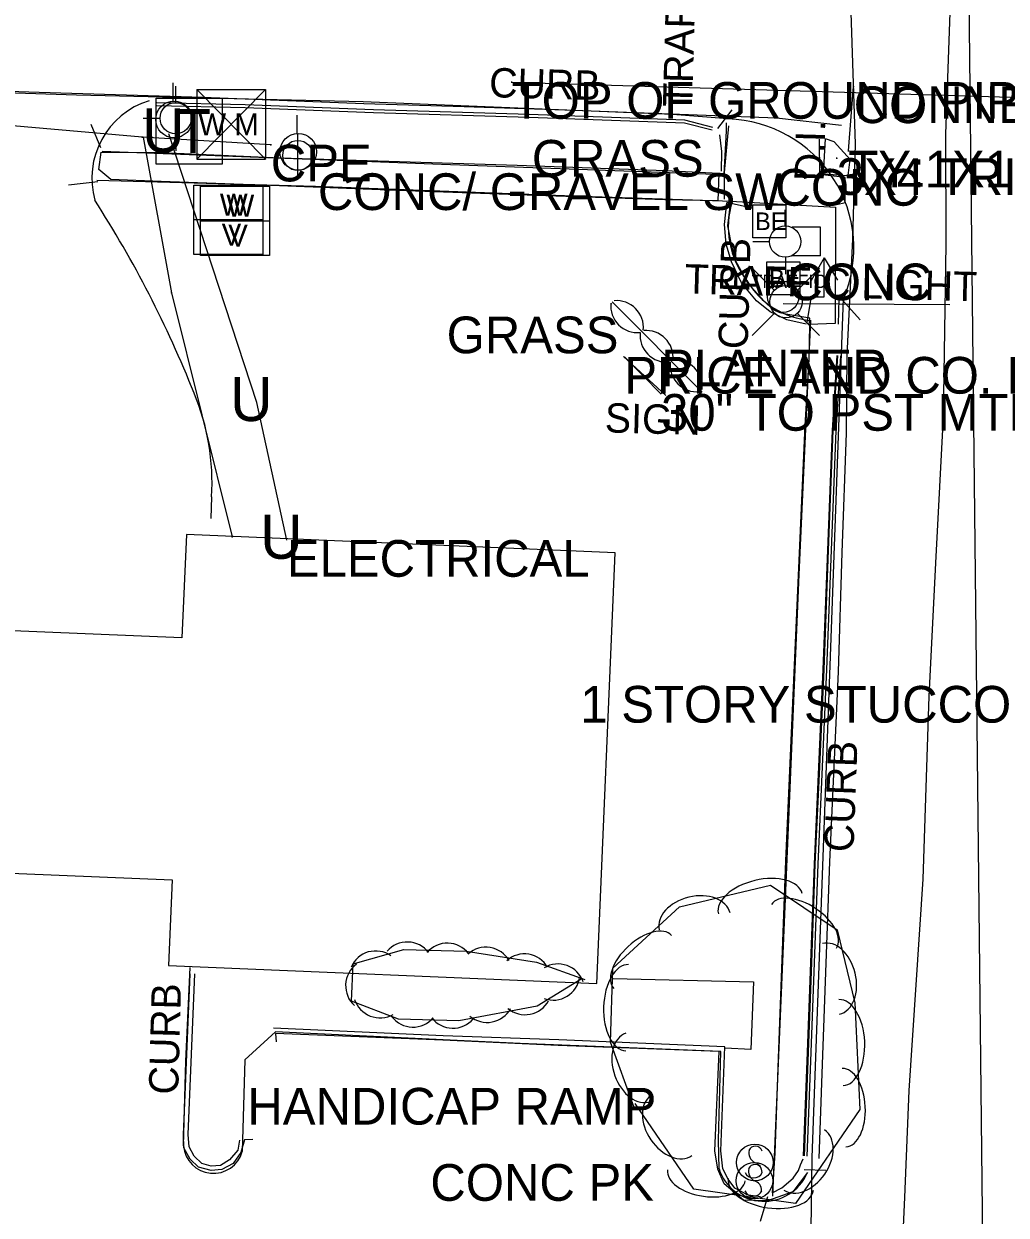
# Model space of a CAD drawing. Extents: x 978516 to 993312, y 1836504 to 1846212.
# Drawn here: x 992368 to 992501.8, y 1843226.3 to 1843388.6 of the extents above; entities that cross this region are included whole.
import ezdxf

# ---------------------------------------------------------------- set-up
doc = ezdxf.new("R2010")
doc.units = 0
for name, color, linetype in [('Default', 7, 'Continuous'), ('S_BASELINE', 7, 'Continuous'), ('S_BUILDING', 7, 'Continuous'), ('S_CURB', 7, 'Continuous'), ('S_CURB_ANNOT', 7, 'Continuous'), ('S_DRG_PT_SYM', 7, 'Continuous'), ('S_DRIVEWAY', 7, 'Continuous'), ('S_DROP_INLET', 7, 'Continuous'), ('S_DROP_INLET_ANNOT', 7, 'Continuous'), ('S_EDGE_CONCRETE', 7, 'Continuous'), ('S_EDGE_PAVEMENT', 7, 'Continuous'), ('S_ELECTRIC_UTILITIES', 7, 'Continuous'), ('S_GAS_UTILITIES', 7, 'Continuous'), ('S_GAS_UTILITIES_ANNOT', 7, 'Continuous'), ('S_PARKING', 7, 'Continuous'), ('S_PAVEMENT_CROWN', 7, 'Continuous'), ('S_SIDEWALK', 7, 'Continuous'), ('S_SIGN', 7, 'Continuous'), ('S_SIGN_ANNOT', 7, 'Continuous'), ('S_STORM_SEWER', 7, 'Continuous'), ('S_STORM_SEWER_ANNOT', 7, 'Continuous'), ('S_SURVEY_TEXT_ANNOT', 7, 'Continuous'), ('S_TELEPHONE_UTILITIES', 7, 'Continuous'), ('S_TRAFFIC_SIGNAL_ANNOT', 7, 'Continuous'), ('S_TREE', 7, 'Continuous'), ('S_UNDERGROUND_CABLE', 7, 'Continuous'), ('S_UNDERGROUND_CABLE_ANNOT', 7, 'Continuous'), ('S_UTILITY_POLE', 7, 'Continuous'), ('S_UTL_PT_SYM', 7, 'Continuous'), ('S_WATER_UTILITIES', 7, 'Continuous')]:
    doc.layers.add(name, color=color, linetype=linetype)

msp = doc.modelspace()

# ---------------------------------------------------------------- linework, layer by layer
at = {"layer": 'S_BASELINE'}
msp.add_line((992491.43, 1843870.1), (992499.58, 1843129.46), dxfattribs=at)
at = {"layer": 'S_BUILDING'}
msp.add_lwpolyline([(992387.68, 1843260.35), (992446.05, 1843257.87), (992448.54, 1843316.56), (992390.13, 1843319.04), (992389.53, 1843304.94), (992364.24, 1843306.02), (992362.84, 1843273.06), (992388.18, 1843271.98)], close=True, dxfattribs=at)
at = {"layer": 'S_CURB'}
for points in [[(992461.76, 1843374.1), (992457.97, 1843375.05), (992436.8, 1843375.84), (992415.61, 1843376.49), (992398.14, 1843377.15), (992386.1, 1843377.44)], [(992461.86, 1843374.49), (992458.03, 1843375.45), (992436.82, 1843376.24), (992415.62, 1843376.89), (992398.15, 1843377.55), (992386.11, 1843377.84)], [(992462.51, 1843374.34), (992464.47, 1843376.9)], [(992378.49, 1843371.69), (992377.17, 1843374.88)], [(992463.04, 1843368.53), (992463.07, 1843371.22), (992462.79, 1843373.49)], [(992378.08, 1843367.07), (992374.08, 1843366.61)], [(992474.55, 1843347.7), (992471.91, 1843348.28), (992469.67, 1843349.36), (992467.81, 1843350.86), (992465.73, 1843353.32), (992464.39, 1843356.17), (992463.65, 1843358.57), (992463.42, 1843361.25), (992463.73, 1843364.21)], [(992463.75, 1843364.29), (992467.14, 1843363.55)], [(992474.68, 1843347.91), (992475.28, 1843351.52)], [(992479.11, 1843351.41), (992481.89, 1843348.27)], [(992479.01, 1843351.15), (992478.93, 1843347.68)], [(992478.84, 1843343.41), (992478.19, 1843333.19), (992477.57, 1843316.92), (992476.94, 1843300.64), (992476.35, 1843287.39), (992475.75, 1843274.14), (992475.26, 1843260.72), (992474.76, 1843247.3), (992474.26, 1843234.39)], [(992479.24, 1843343.39), (992478.59, 1843333.17), (992477.97, 1843316.9), (992477.34, 1843300.63), (992476.75, 1843287.38), (992476.15, 1843274.13), (992475.66, 1843260.7), (992475.16, 1843247.28), (992474.66, 1843234.38)], [(992397.36, 1843236.54), (992397.14, 1843235.17), (992396.02, 1843233.84), (992394.76, 1843233.1), (992393.49, 1843233.01), (992392.23, 1843233.36), (992391.19, 1843234.34), (992390.49, 1843235.62), (992390.36, 1843237.3), (992391.29, 1843259.21)], [(992468.33, 1843228.81), (992466.38, 1843229.09), (992466.47, 1843229.16), (992464.85, 1843230.02), (992463.93, 1843231.23), (992463.21, 1843232.65), (992462.94, 1843235.09), (992463.48, 1843249.24), (992440.87, 1843250.2), (992425.09, 1843250.74), (992402.01, 1843251.81)], [(992474.27, 1843232.53), (992477.22, 1843232.45)], [(992469.29, 1843228.81), (992468.29, 1843225.47)]]:
    msp.add_lwpolyline(points, dxfattribs=at)
at = {"layer": 'S_DRG_PT_SYM'}
msp.add_lwpolyline([(992478.71, 1843370.29), (992478.71, 1843370.33), (992478.71, 1843370.29), (992478.66, 1843370.29), (992478.71, 1843370.29), (992478.71, 1843370.23), (992478.71, 1843370.29), (992478.76, 1843370.29)], dxfattribs=at)
at = {"layer": 'S_DRIVEWAY'}
msp.add_lwpolyline([(992474.73, 1843232.14), (992472.74, 1843229.52), (992469.28, 1843228.26), (992466.01, 1843228.38), (992463.37, 1843230.6)], dxfattribs=at)
at = {"layer": 'S_DROP_INLET'}
msp.add_lwpolyline([(992477.14, 1843372.93), (992476.88, 1843368.15), (992480.29, 1843367.93), (992480.56, 1843370.12), (992478.38, 1843372.54), (992477.2, 1843372.92)], dxfattribs=at)
at = {"layer": 'S_EDGE_CONCRETE'}
for points in [[(992463.43, 1843364.73), (992463.45, 1843368.36), (992464, 1843374.72)], [(992478.75, 1843363.98), (992479.87, 1843364.26), (992479.88, 1843367.67), (992476.4, 1843368.06), (992476.37, 1843372.9)]]:
    msp.add_lwpolyline(points, dxfattribs=at)
msp.add_lwpolyline([(992478.5, 1843347.79), (992474.96, 1843347.65), (992475.06, 1843348.51), (992471.79, 1843349.05), (992471.02, 1843349.25), (992470.06, 1843349.64), (992468.81, 1843350.82), (992466.62, 1843353.26), (992464.92, 1843356.35), (992464.44, 1843358.3), (992463.89, 1843361.08), (992464.28, 1843364.42), (992478.55, 1843363.63)], close=True, dxfattribs=at)
at = {"layer": 'S_EDGE_PAVEMENT'}
for points in [[(992480.65, 1843390.13), (992481.25, 1843372.19), (992480.85, 1843359.25), (992480.08, 1843343.45), (992479.98, 1843332.82), (992479.43, 1843316.57), (992478.89, 1843300.32), (992478.31, 1843287.38), (992477.74, 1843274.44), (992477.23, 1843260.67), (992476.73, 1843246.91), (992476.28, 1843234.04)], [(992463.93, 1843375.63), (992456.33, 1843376.26), (992414.2, 1843377.98), (992375.17, 1843378.86), (992348.72, 1843379.74), (992337.57, 1843380.35), (992300.48, 1843381.41), (992269.4, 1843382.01), (992176.55, 1843385.64)], [(992479.35, 1843374.75), (992470.53, 1843375.75), (992456.11, 1843376.29), (992441.69, 1843376.84), (992427.98, 1843377.27), (992414.28, 1843377.7), (992392.38, 1843378.55), (992370.09, 1843379.26), (992347.81, 1843379.98), (992323.02, 1843381.11), (992310.07, 1843381.45), (992297.12, 1843381.79), (992284.17, 1843382.13), (992271.22, 1843382.47), (992253.23, 1843383.19), (992235.23, 1843383.91), (992216.97, 1843384.32), (992198.7, 1843384.73)], [(992474.97, 1843204.89), (992475.38, 1843234.16), (992477.92, 1843303.68), (992479.66, 1843351.16)]]:
    msp.add_lwpolyline(points, dxfattribs=at)
msp.add_arc((992463.41, 1843358), 17.64, 337.1488, 88.2913, dxfattribs=at)
at = {"layer": 'S_ELECTRIC_UTILITIES'}
for points in [[(992467.28, 1843359.45), (992467.28, 1843363.95), (992471.78, 1843363.95), (992471.78, 1843359.45)], [(992469.19, 1843351.68), (992469.19, 1843356.18), (992473.69, 1843356.18), (992473.69, 1843351.68)]]:
    msp.add_lwpolyline(points, close=True, dxfattribs=at)
at = {"layer": 'S_GAS_UTILITIES'}
for p, q in [((992384.09, 1843373.17), (992362.65, 1843375.04)), ((992401.63, 1843372.13), (992384.09, 1843373.17)), ((992384.22, 1843373.16), (992388.1, 1843351.95)), ((992388.1, 1843351.95), (992396.37, 1843318.72))]:
    msp.add_line(p, q, dxfattribs=at)
at = {"layer": 'S_PARKING'}
for points in [[(992393.56, 1843324.16), (992393.48, 1843321.21)], [(992399.19, 1843236.64), (992398.05, 1843236.57), (992397.54, 1843234.87), (992396.48, 1843233.37), (992394.94, 1843232.56), (992393.51, 1843232.41), (992391.78, 1843232.87), (992390.64, 1843233.95), (992389.8, 1843235.49), (992389.72, 1843237.27), (992390.64, 1843259.2)], [(992389.75, 1843235.77), (992390.06, 1843247.31), (992390.66, 1843260.07)], [(992462.68, 1843232.63), (992462.63, 1843236.55), (992462.95, 1843248.63), (992435.6, 1843249.72), (992402.27, 1843251.29), (992398.11, 1843247.49), (992397.74, 1843235.01)], [(992463.37, 1843230.61), (992462.53, 1843232.6), (992462.13, 1843235.09), (992462.68, 1843248.6), (992440.75, 1843249.44), (992425.06, 1843250.15), (992402.29, 1843251.08), (992402.36, 1843249.94)]]:
    msp.add_lwpolyline(points, dxfattribs=at)
for centre, radius, start, end in [((992362.44, 1843326.18), 31.18, 356.2751, 22.8453), ((992393.81, 1843236.1), 4.08, 184.6372, 344.5547), ((992468.8, 1843234.66), 6.45, 198.415, 336.1859)]:
    msp.add_arc(centre, radius, start, end, dxfattribs=at)
for centre, major_axis, ratio, start_param, end_param in [((992388.3, 1843367.58), (-8.35, -7.27), 0.996163, 4.29708, 5.841914), ((992250.96, 1843282.66), (-62.89, 137.77), 0.996042, 4.662049, 4.857506)]:
    msp.add_ellipse(centre, major_axis=major_axis, ratio=ratio, start_param=start_param, end_param=end_param, dxfattribs=at)
at = {"layer": 'S_PAVEMENT_CROWN'}
msp.add_lwpolyline([(992494.22, 1843392.67), (992493.55, 1843373.61), (992493.6, 1843358.6), (992493.2, 1843335.06), (992492.22, 1843316.03), (992491.24, 1843297.01), (992490.46, 1843272.09), (992489.49, 1843257.7), (992488.53, 1843243.31), (992487.97, 1843228.71), (992487.38, 1843215.85), (992486.79, 1843202.98), (992487.13, 1843184.28), (992487.26, 1843176.7)], dxfattribs=at)
at = {"layer": 'S_SIDEWALK'}
for points in [[(992378.64, 1843371.26), (992424.88, 1843369.47), (992463.37, 1843368.07), (992463.68, 1843374.02), (992463.69, 1843375.11)], [(992377.91, 1843367.31), (992407.72, 1843366.47), (992444.02, 1843365.14), (992464.51, 1843364.45)], [(992475.14, 1843348.21), (992473.54, 1843313.59), (992471.49, 1843265.15), (992469.98, 1843228.91)], [(992475.02, 1843347.54), (992474.92, 1843342.92), (992474.35, 1843333.88), (992473.64, 1843317.55), (992472.93, 1843301.22), (992472.34, 1843287.91), (992471.76, 1843274.6), (992471.25, 1843261.16), (992470.75, 1843247.73), (992470.28, 1843234.78), (992469.91, 1843229.37), (992471.26, 1843230.05), (992472.79, 1843231.36), (992473.53, 1843232.43), (992473.79, 1843233.17), (992474.14, 1843233.98)], [(992478.74, 1843343.42), (992478.09, 1843333.2), (992477.47, 1843316.92), (992476.84, 1843300.65), (992476.25, 1843287.4), (992475.65, 1843274.15), (992475.16, 1843260.72), (992474.66, 1843247.3), (992474.16, 1843234.39)], [(992448.26, 1843258.58), (992467.39, 1843258.11), (992467.01, 1843248.89), (992463.54, 1843249.07)]]:
    msp.add_lwpolyline(points, dxfattribs=at)
msp.add_lwpolyline([(992462.52, 1843364.48), (992455.29, 1843364.61), (992439.11, 1843365.17), (992418.78, 1843365.9), (992402.82, 1843366.54), (992386.69, 1843367.12), (992379.85, 1843367.37), (992378.22, 1843368.77), (992378.5, 1843371.12), (992386.78, 1843371.05), (992402.95, 1843370.32), (992419.16, 1843369.86), (992435.17, 1843369.34), (992455.39, 1843368.6), (992462.64, 1843368.27)], close=True, dxfattribs=at)
for centre, radius, start, end in [((992475.64, 1843360.89), 11.69, 162.2435, 218.3534), ((992476.05, 1843359.29), 11.12, 210.5892, 265.347)]:
    msp.add_arc(centre, radius, start, end, dxfattribs=at)
at = {"layer": 'S_SIGN'}
msp.add_line((992454.79, 1843338.17), (992449.79, 1843343.22), dxfattribs=at)
msp.add_lwpolyline([(992449.65, 1843343.26), (992455.42, 1843337.99)], dxfattribs=at)
for centre in [(992467.56, 1843233.5), (992467.51, 1843231.02)]:
    msp.add_circle(centre, 2.49, dxfattribs=at)
for centre, radius, start, end in [((992468.24, 1843234.83), 1.5, 167.1196, 241.9813), ((992467.63, 1843234.77), 0.95, 16.5258, 156.8957), ((992467.58, 1843232.28), 0.95, 16.5258, 156.8957), ((992467.14, 1843232.16), 1.4, 358.6529, 73.7063), ((992467.4, 1843232.68), 1.28, 204.641, 335.359), ((992468.19, 1843232.34), 1.5, 167.1196, 241.9813), ((992467.35, 1843230.19), 1.28, 204.641, 335.359), ((992467.09, 1843229.67), 1.4, 358.6529, 73.7063)]:
    msp.add_arc(centre, radius, start, end, dxfattribs=at)
at = {"layer": 'S_STORM_SEWER'}
for p, q in [((992434.44, 1843380.66), (992576.6, 1843376.33)), ((992480.3, 1843371.3), (992481.02, 1843380.07))]:
    msp.add_line(p, q, dxfattribs=at)
at = {"layer": 'S_TELEPHONE_UTILITIES'}
msp.add_lwpolyline([(992386.01, 1843369.49), (992386.01, 1843378.49), (992395.01, 1843378.49), (992395.01, 1843369.49)], close=True, dxfattribs=at)
at = {"layer": 'S_TREE'}
for points in [[(992447.99, 1843350.5), (992448.06, 1843350.43)], [(992448.15, 1843350.74), (992460.37, 1843338.43)], [(992451.11, 1843241), (992447.92, 1843249.87), (992448.24, 1843259.99), (992457.3, 1843268.3), (992469.7, 1843271.28), (992478.76, 1843265.21), (992481.17, 1843255.23), (992481.85, 1843240.71), (992473.11, 1843227.91), (992459.24, 1843229.86), (992451.26, 1843241.52)], [(992443.89, 1843258.46), (992437.9, 1843254.79), (992427.23, 1843252.79), (992419.01, 1843253.01), (992412.62, 1843255.49), (992412.87, 1843260.57), (992419.73, 1843262.53), (992428.23, 1843262.3), (992437.83, 1843260.78), (992444.41, 1843258.41)]]:
    msp.add_lwpolyline(points, dxfattribs=at)
for centre, start, end in [((992451.58, 1843350.17), 174.0035, 275.6004), ((992448.74, 1843347.25), 354.0035, 95.6004), ((992455.56, 1843346.16), 174.0035, 275.6004), ((992452.78, 1843343.18), 354.0035, 95.6004), ((992459.65, 1843342.12), 174.0035, 275.6004), ((992456.76, 1843339.18), 354.0035, 95.6004), ((992415.91, 1843258.67), 55.1123, 156.7092), ((992420.23, 1843259.89), 37.647, 139.2439), ((992425.67, 1843259.74), 37.647, 139.2439), ((992430.94, 1843259.18), 30.2367, 131.8336), ((992415.46, 1843257.57), 126.4321, 228.029), ((992436.19, 1843258.27), 30.2367, 131.8336), ((992440.75, 1843256.9), 19.4054, 121.0023), ((992440.09, 1843259.25), 250.6992, 352.2961), ((992416.5, 1843256.84), 197.9838, 299.5807), ((992431.1, 1843256.22), 229.8335, 331.4305), ((992436.28, 1843257.27), 229.8335, 331.4305), ((992421, 1843255.58), 217.647, 319.2439), ((992426.44, 1843255.43), 217.647, 319.2439)]:
    msp.add_arc(centre, 3.64, start, end, dxfattribs=at)
for centre, major_axis, ratio in [((992468.3, 1843268.76), (-5.71, -1.37), 0.55008), ((992459.36, 1843266.34), (-4.82, -1.16), 0.685311), ((992474.26, 1843265.67), (-4.44, 2.98), 0.540699), ((992452.28, 1843260.81), (-3.94, -3.62), 0.540699), ((992477.93, 1843258.51), (-1.16, 4.82), 0.685311), ((992450.19, 1843254.59), (-0.18, -5.87), 0.55008), ((992479.3, 1843249.83), (-0.28, 5.86), 0.55008), ((992451.68, 1843246.47), (1.67, -4.66), 0.685311), ((992479.72, 1843240.97), (-0.25, 5.34), 0.540699), ((992456.2, 1843238.52), (2.8, -4.09), 0.685311), ((992474.28, 1843233.84), (2.79, 4.09), 0.685311), ((992460.96, 1843231.76), (5.29, -0.74), 0.540699), ((992469.74, 1843230.53), (5.81, -0.81), 0.55008)]:
    msp.add_ellipse(centre, major_axis=major_axis, ratio=ratio, start_param=3.141593, end_param=6.283185, dxfattribs=at)
at = {"layer": 'S_UNDERGROUND_CABLE'}
for p, q in [((992399.71, 1843337.03), (992387.73, 1843373.62)), ((992403.81, 1843318.28), (992399.71, 1843337.03))]:
    msp.add_line(p, q, dxfattribs=at)
at = {"layer": 'S_UTILITY_POLE'}
for p, q in [((992388.31, 1843378.08), (992388.31, 1843380.56)), ((992388.67, 1843377.85), (992388.67, 1843380.1)), ((992386.58, 1843375.72), (992384.25, 1843375.72)), ((992405.23, 1843373.69), (992405.23, 1843376.17)), ((992388.75, 1843371.31), (992388.75, 1843373.63)), ((992405.31, 1843367.73), (992405.31, 1843373.52)), ((992471.7, 1843361.04), (992471.7, 1843363.28)), ((992476.5, 1843360.88), (992472.63, 1843360.88)), ((992476.5, 1843356.97), (992476.5, 1843360.88)), ((992469.61, 1843358.9), (992467.28, 1843358.9)), ((992471.78, 1843354.49), (992471.78, 1843356.81)), ((992476.5, 1843356.97), (992472.63, 1843356.97)), ((992477.02, 1843356.72), (992475.23, 1843353.62)), ((992477.02, 1843351.41), (992477.02, 1843356.72)), ((992477.02, 1843356.72), (992478.8, 1843353.66)), ((992470.21, 1843352.32), (992467.22, 1843355.3)), ((992473.38, 1843352.32), (992476.37, 1843355.3)), ((992473.49, 1843351.41), (992477.02, 1843351.41)), ((992470.21, 1843349.14), (992467.22, 1843346.16)), ((992473.38, 1843349.14), (992476.37, 1843346.16))]:
    msp.add_line(p, q, dxfattribs=at)
msp.add_lwpolyline([(992471.4, 1843350.52), (992494.13, 1843350.35)], dxfattribs=at)
for centre, radius in [((992388.45, 1843375.57), 2.5), ((992388.67, 1843375.74), 2.13), ((992405.37, 1843371.17), 2.5), ((992405.31, 1843370.66), 2.05), ((992471.7, 1843358.93), 2.13), ((992471.42, 1843351.4), 2.13), ((992471.8, 1843350.74), 2.21)]:
    msp.add_circle(centre, radius, dxfattribs=at)
at = {"layer": 'S_UTL_PT_SYM'}
for points in [[(992434.44, 1843380.66), (992434.44, 1843380.71), (992434.44, 1843380.66), (992434.39, 1843380.66), (992434.44, 1843380.66), (992434.44, 1843380.61), (992434.44, 1843380.66), (992434.49, 1843380.66)], [(992481.02, 1843380.07), (992481.02, 1843380.12), (992481.02, 1843380.07), (992480.97, 1843380.07), (992481.02, 1843380.07), (992481.02, 1843380.02), (992481.02, 1843380.07), (992481.07, 1843380.07)], [(992384.09, 1843373.17), (992384.09, 1843373.22), (992384.09, 1843373.17), (992384.04, 1843373.17), (992384.09, 1843373.17), (992384.09, 1843373.12), (992384.09, 1843373.17), (992384.14, 1843373.17)], [(992384.22, 1843373.16), (992384.22, 1843373.21), (992384.22, 1843373.16), (992384.17, 1843373.16), (992384.22, 1843373.16), (992384.22, 1843373.11), (992384.22, 1843373.16), (992384.27, 1843373.16)], [(992401.63, 1843372.13), (992401.63, 1843372.18), (992401.63, 1843372.13), (992401.58, 1843372.13), (992401.63, 1843372.13), (992401.63, 1843372.08), (992401.63, 1843372.13), (992401.68, 1843372.13)], [(992480.3, 1843371.3), (992480.3, 1843371.35), (992480.3, 1843371.3), (992480.25, 1843371.3), (992480.3, 1843371.3), (992480.3, 1843371.25), (992480.3, 1843371.3), (992480.35, 1843371.3)], [(992478.71, 1843370.29), (992478.71, 1843370.33), (992478.71, 1843370.29), (992478.66, 1843370.29), (992478.71, 1843370.29), (992478.71, 1843370.23), (992478.71, 1843370.29), (992478.76, 1843370.29)], [(992388.1, 1843351.95), (992388.1, 1843352), (992388.1, 1843351.95), (992388.05, 1843351.95), (992388.1, 1843351.95), (992388.1, 1843351.9), (992388.1, 1843351.95), (992388.15, 1843351.95)], [(992396.37, 1843318.72), (992396.37, 1843318.77), (992396.37, 1843318.72), (992396.32, 1843318.72), (992396.37, 1843318.72), (992396.37, 1843318.67), (992396.37, 1843318.72), (992396.42, 1843318.72)]]:
    msp.add_lwpolyline(points, dxfattribs=at)
at = {"layer": 'S_WATER_UTILITIES'}
for p, q in [((992391.55, 1843379.64), (992400.89, 1843379.64)), ((992391.55, 1843379.64), (992391.55, 1843370.14)), ((992391.55, 1843379.64), (992400.89, 1843370.14)), ((992400.89, 1843379.64), (992391.55, 1843370.14)), ((992400.89, 1843379.64), (992400.89, 1843370.14)), ((992391.55, 1843370.14), (992400.89, 1843370.14)), ((992391.14, 1843366.6), (992400.56, 1843366.6)), ((992391.14, 1843357.19), (992391.14, 1843366.6)), ((992392.04, 1843366.47), (992401.46, 1843366.47)), ((992392.04, 1843357.05), (992392.04, 1843366.47)), ((992400.56, 1843366.6), (992400.56, 1843357.19)), ((992401.46, 1843366.47), (992401.46, 1843357.05)), ((992391.14, 1843361.92), (992400.56, 1843361.92)), ((992392.04, 1843361.78), (992401.46, 1843361.78)), ((992400.56, 1843357.19), (992391.14, 1843357.19)), ((992401.46, 1843357.05), (992392.04, 1843357.05))]:
    msp.add_line(p, q, dxfattribs=at)

# ---------------------------------------------------------------- texts
at = {"layer": 'Default'}
for p in [(992384.1, 1843371.07), (992396.08, 1843334.49), (992400.18, 1843315.73)]:
    msp.add_text('U', height=6, dxfattribs=at).set_placement(p)
at = {"layer": 'S_CURB_ANNOT'}
for rotation, p in [(358.4454, (992431.33, 1843378.61)), (88.4454, (992466.58, 1843344.24)), (87.831, (992480.99, 1843275.72)), (88.4454, (992389, 1843242.71))]:
    msp.add_text('CURB', height=4, rotation=rotation, dxfattribs=at).set_placement(p)
at = {"layer": 'S_DROP_INLET_ANNOT'}
msp.add_text('D.I.', height=4, rotation=88.4454, dxfattribs=at).set_placement((992476.94, 1843367.1))
msp.add_text('3X4 TRIANGLE .20 SPACING', height=5, dxfattribs=at).set_placement((992478.71, 1843365.29))
at = {"layer": 'S_ELECTRIC_UTILITIES'}
for p in [(992467.59, 1843360.5), (992469.51, 1843352.73)]:
    msp.add_text('BE', height=2.4, dxfattribs=at).set_placement(p)
at = {"layer": 'S_GAS_UTILITIES_ANNOT'}
msp.add_text('CPE', height=5, dxfattribs=at).set_placement((992401.63, 1843367.13))
at = {"layer": 'S_SIGN_ANNOT'}
for s, p in [('PRICE AND CO. INSURANCE', (992449.79, 1843338.22)), ('30" TO PST MTL PLAS ELEC', (992454.79, 1843333.17))]:
    msp.add_text(s, height=5, dxfattribs=at).set_placement(p)
msp.add_text('SIGN', height=4, rotation=358.4454, dxfattribs=at).set_placement((992447.09, 1843332.95))
at = {"layer": 'S_STORM_SEWER_ANNOT'}
for s, p in [('TOP OF GROUND PIPE UNDER GROUND', (992434.44, 1843375.66)), ('CONNECTS UNDER GROUND', (992481.02, 1843375.07)), ('TY:1X1 BOX HOMEMADE', (992480.3, 1843366.3))]:
    msp.add_text(s, height=5, dxfattribs=at).set_placement(p)
at = {"layer": 'S_SURVEY_TEXT_ANNOT'}
for s, p in [('GRASS', (992437.19, 1843367.77)), (' CONC/ GRAVEL SW', (992406.19, 1843363.23)), ('CONC', (992470.37, 1843363.82)), ('CONC', (992471.99, 1843350.94)), ('GRASS', (992425.58, 1843343.72)), ('PLANTER', (992454.81, 1843339.21)), ('1 STORY STUCCO AND ROCK', (992443.79, 1843293.41)), ('HANDICAP RAMP', (992398.43, 1843238.66)), ('CONC PK', (992423.36, 1843228.28))]:
    msp.add_text(s, height=5, dxfattribs=at).set_placement(p)
at = {"layer": 'S_TELEPHONE_UTILITIES'}
msp.add_text('T', height=6, dxfattribs=at).set_placement((992388.57, 1843370.99))
at = {"layer": 'S_TRAFFIC_SIGNAL_ANNOT'}
for rotation, p in [(88.4454, (992459.03, 1843377.22)), (358.4454, (992457.97, 1843351.87))]:
    msp.add_text('TRAFFIC LIGHT', height=4.0004, rotation=rotation, dxfattribs=at).set_placement(p)
at = {"layer": 'S_UNDERGROUND_CABLE_ANNOT'}
msp.add_text('ELECTRICAL', height=5, dxfattribs=at).set_placement((992403.81, 1843313.28))
at = {"layer": 'S_UTILITY_POLE'}
msp.add_text('TRAFFIC', height=1.8, dxfattribs=at).set_placement((992467.12, 1843352.62))
at = {"layer": 'S_WATER_UTILITIES'}
for s, p in [('W M', (992391.76, 1843373.4)), ('W', (992394.69, 1843362.45)), ('W', (992395.59, 1843362.31)), ('V', (992394.93, 1843358.38)), ('V', (992395.83, 1843358.25))]:
    msp.add_text(s, height=3, dxfattribs=at).set_placement(p)

doc.saveas('drawing.dxf')
